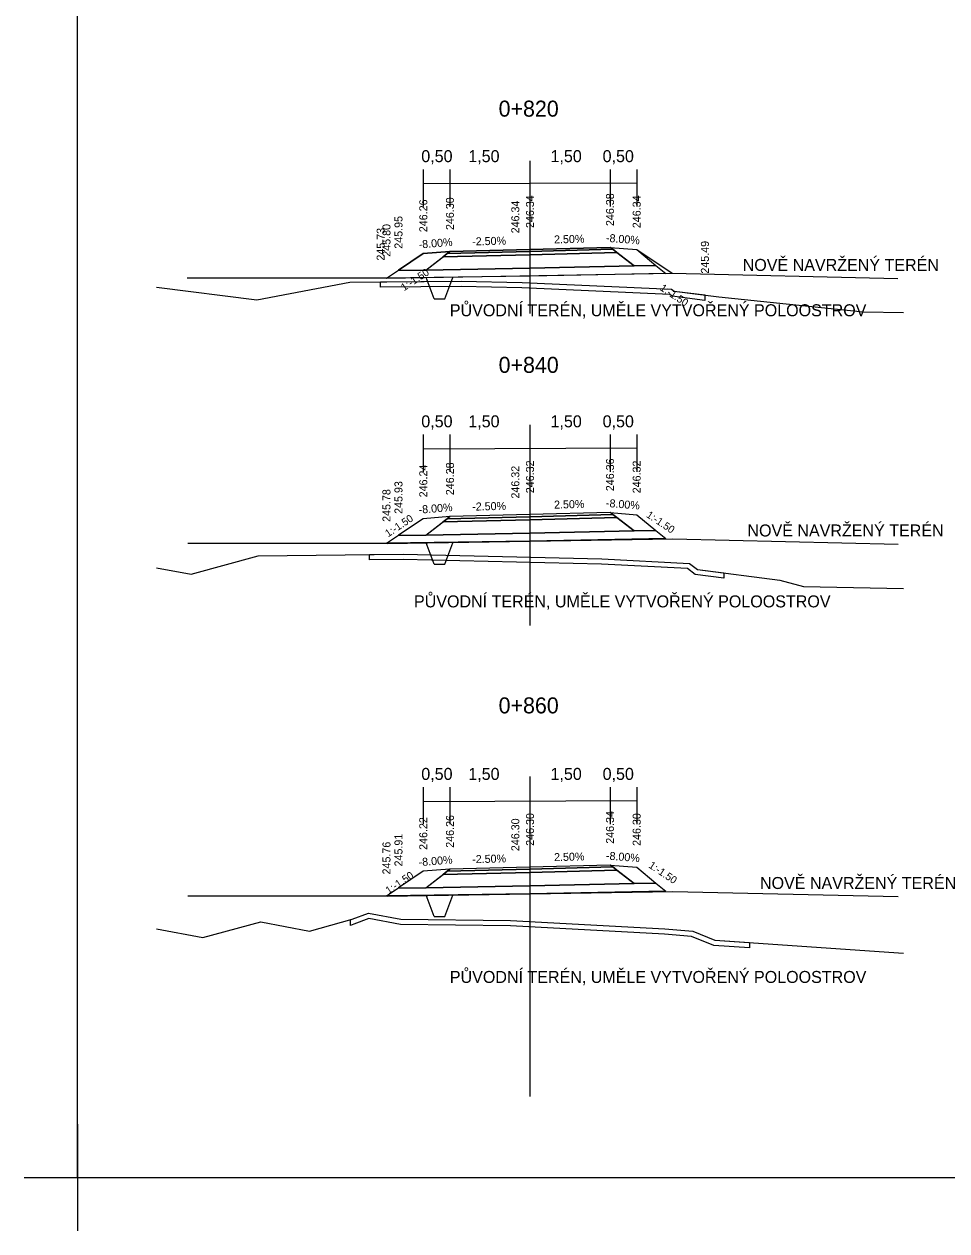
# Model space of a CAD drawing. Extents: x -552501 to -552394, y -1029983 to -1029892.
# Drawn here: x -552500.76 to -552483.46, y -1029983.45 to -1029960.83 of the extents above; entities that cross this region are included whole.
import ezdxf

# ---------------------------------------------------------------- set-up
doc = ezdxf.new("R2010")
doc.units = 0
for name, color, linetype in [('1', 7, 'Continuous'), ('16', 7, 'Continuous'), ('60', 7, 'Continuous'), ('9', 7, 'Continuous'), ('FORMATY', 7, 'Continuous'), ('Implicitní', 7, 'Continuous'), ('rámeček', 7, 'Continuous')]:
    doc.layers.add(name, color=color, linetype=linetype)

msp = doc.modelspace()

# ---------------------------------------------------------------- linework, layer by layer
for p, q in [((-552493.964, -1029965.59), (-552497.7, -1029965.59)), ((-552493.07, -1029965.98), (-552493.22, -1029965.58)), ((-552492.87, -1029965.98), (-552492.72, -1029965.58)), ((-552493.07, -1029965.98), (-552492.87, -1029965.98)), ((-552493.953, -1029970.568), (-552497.689, -1029970.568)), ((-552493.07, -1029970.95), (-552493.22, -1029970.55)), ((-552492.87, -1029970.95), (-552492.72, -1029970.55)), ((-552493.07, -1029970.95), (-552492.87, -1029970.95)), ((-552493.953, -1029977.176), (-552497.689, -1029977.176)), ((-552493.07, -1029977.559), (-552493.22, -1029977.159)), ((-552492.87, -1029977.559), (-552492.72, -1029977.159)), ((-552493.07, -1029977.559), (-552492.87, -1029977.559))]:
    msp.add_line(p, q)
for points in [[(-552493.964, -1029965.59), (-552493.739, -1029965.44), (-552493.274, -1029965.13), (-552492.774, -1029965.09), (-552491.274, -1029965.052), (-552489.774, -1029965.015), (-552489.274, -1029965.055), (-552488.606, -1029965.5)], [(-552493.964, -1029965.59), (-552488.606, -1029965.5), (-552484.38, -1029965.597)], [(-552498.274, -1029965.759), (-552496.392, -1029966), (-552494.648, -1029965.669), (-552492.561, -1029965.645), (-552491.42, -1029965.671), (-552488.619, -1029965.797), (-552488.57, -1029965.834), (-552487.737, -1029965.94), (-552485.026, -1029966.224), (-552484.274, -1029966.237)], [(-552493.953, -1029970.568), (-552488.596, -1029970.478), (-552484.37, -1029970.575)], [(-552498.274, -1029971.02), (-552497.623, -1029971.142), (-552496.369, -1029970.798), (-552493.653, -1029970.766), (-552489.927, -1029970.85), (-552488.286, -1029970.938), (-552488.137, -1029971.053), (-552486.59, -1029971.25), (-552486.147, -1029971.371), (-552484.274, -1029971.407)], [(-552493.953, -1029977.176), (-552488.596, -1029977.087), (-552484.37, -1029977.183)], [(-552498.274, -1029977.787), (-552497.407, -1029977.95), (-552496.321, -1029977.656), (-552495.405, -1029977.831), (-552494.604, -1029977.609), (-552494.301, -1029977.493), (-552493.693, -1029977.605), (-552491.638, -1029977.633), (-552488.747, -1029977.787), (-552488.22, -1029977.833), (-552487.809, -1029977.999), (-552484.274, -1029978.247)]]:
    msp.add_lwpolyline(points)
for points in [[(-552492.774, -1029965.09), (-552493.274, -1029965.13), (-552493.739, -1029965.44), (-552493.225, -1029965.44)], [(-552491.275, -1029965.092), (-552492.825, -1029965.13), (-552492.903, -1029965.19), (-552491.275, -1029965.152), (-552489.646, -1029965.109), (-552489.723, -1029965.049), (-552491.275, -1029965.092), (-552489.723, -1029965.049), (-552489.774, -1029965.015), (-552491.274, -1029965.052), (-552492.774, -1029965.09), (-552492.825, -1029965.13)], [(-552492.903, -1029965.19), (-552492.825, -1029965.13), (-552491.275, -1029965.092), (-552489.723, -1029965.049), (-552489.646, -1029965.109), (-552491.275, -1029965.152)], [(-552489.774, -1029965.015), (-552489.274, -1029965.055), (-552488.913, -1029965.353), (-552489.324, -1029965.359), (-552489.646, -1029965.109), (-552489.723, -1029965.049)], [(-552493.225, -1029965.44), (-552492.903, -1029965.19), (-552491.275, -1029965.152), (-552489.646, -1029965.109), (-552489.324, -1029965.359), (-552491.275, -1029965.402)], [(-552493.964, -1029965.59), (-552493.739, -1029965.44), (-552493.225, -1029965.44), (-552491.275, -1029965.402), (-552489.324, -1029965.359), (-552488.913, -1029965.353), (-552488.728, -1029965.503), (-552491.275, -1029965.552)], [(-552494.073, -1029965.663), (-552492.561, -1029965.645), (-552491.42, -1029965.671), (-552488.619, -1029965.797), (-552488.57, -1029965.834), (-552487.995, -1029965.907), (-552487.995, -1029966.008), (-552488.609, -1029965.93), (-552488.654, -1029965.895), (-552491.424, -1029965.771), (-552492.562, -1029965.745), (-552494.073, -1029965.763)], [(-552492.774, -1029970.06), (-552493.274, -1029970.1), (-552493.739, -1029970.41), (-552493.225, -1029970.41)], [(-552491.275, -1029970.063), (-552492.825, -1029970.1), (-552492.903, -1029970.16), (-552491.275, -1029970.123), (-552489.646, -1029970.079), (-552489.723, -1029970.019), (-552491.275, -1029970.063), (-552489.723, -1029970.019), (-552489.774, -1029969.985), (-552491.274, -1029970.023), (-552492.774, -1029970.06), (-552492.825, -1029970.1)], [(-552492.903, -1029970.16), (-552492.825, -1029970.1), (-552491.275, -1029970.063), (-552489.723, -1029970.019), (-552489.646, -1029970.079), (-552491.275, -1029970.123)], [(-552489.774, -1029969.985), (-552489.274, -1029970.025), (-552488.913, -1029970.323), (-552489.324, -1029970.329), (-552489.646, -1029970.079), (-552489.723, -1029970.019)], [(-552493.225, -1029970.41), (-552492.903, -1029970.16), (-552491.275, -1029970.123), (-552489.646, -1029970.079), (-552489.324, -1029970.329), (-552491.275, -1029970.373)], [(-552493.964, -1029970.56), (-552493.739, -1029970.41), (-552493.225, -1029970.41), (-552491.275, -1029970.373), (-552489.324, -1029970.329), (-552488.913, -1029970.323), (-552488.728, -1029970.473), (-552491.275, -1029970.523)], [(-552494.283, -1029970.773), (-552493.653, -1029970.766), (-552489.927, -1029970.85), (-552488.286, -1029970.938), (-552488.137, -1029971.053), (-552487.638, -1029971.116), (-552487.638, -1029971.217), (-552488.176, -1029971.149), (-552488.322, -1029971.037), (-552489.931, -1029970.95), (-552493.654, -1029970.866), (-552494.283, -1029970.873)], [(-552491.275, -1029976.672), (-552492.825, -1029976.709), (-552492.903, -1029976.769), (-552491.275, -1029976.732), (-552489.646, -1029976.688), (-552489.723, -1029976.628), (-552491.275, -1029976.672), (-552489.723, -1029976.628), (-552489.774, -1029976.594), (-552491.274, -1029976.632), (-552492.774, -1029976.669), (-552492.825, -1029976.709)], [(-552492.903, -1029976.769), (-552492.825, -1029976.709), (-552491.275, -1029976.672), (-552489.723, -1029976.628), (-552489.646, -1029976.688), (-552491.275, -1029976.732)], [(-552489.774, -1029976.594), (-552489.274, -1029976.634), (-552488.913, -1029976.932), (-552489.324, -1029976.938), (-552489.646, -1029976.688), (-552489.723, -1029976.628)], [(-552492.774, -1029976.669), (-552493.274, -1029976.709), (-552493.739, -1029977.019), (-552493.225, -1029977.019)], [(-552493.225, -1029977.019), (-552492.903, -1029976.769), (-552491.275, -1029976.732), (-552489.646, -1029976.688), (-552489.324, -1029976.938), (-552491.275, -1029976.982)], [(-552493.964, -1029977.169), (-552493.739, -1029977.019), (-552493.225, -1029977.019), (-552491.275, -1029976.982), (-552489.324, -1029976.938), (-552488.913, -1029976.932), (-552488.728, -1029977.082), (-552491.275, -1029977.132)], [(-552494.639, -1029977.619), (-552494.604, -1029977.609), (-552494.301, -1029977.493), (-552493.693, -1029977.605), (-552491.638, -1029977.633), (-552488.747, -1029977.787), (-552488.22, -1029977.833), (-552487.809, -1029977.999), (-552487.158, -1029978.045), (-552487.158, -1029978.145), (-552487.831, -1029978.098), (-552488.244, -1029977.931), (-552488.754, -1029977.887), (-552491.641, -1029977.733), (-552493.703, -1029977.705), (-552494.292, -1029977.597), (-552494.573, -1029977.704), (-552494.639, -1029977.723)]]:
    msp.add_lwpolyline(points, close=True)
at = {"layer": '60'}
for p, q in [((-552491.274, -1029963.394), (-552491.274, -1029966.254)), ((-552491.274, -1029968.343), (-552491.274, -1029972.102)), ((-552491.274, -1029974.93), (-552491.274, -1029980.93))]:
    msp.add_line(p, q, dxfattribs=at)
at = {"layer": '9'}
for p, q in [((-552493.274, -1029963.552), (-552493.274, -1029964.25)), ((-552492.774, -1029963.552), (-552492.774, -1029964.25)), ((-552491.274, -1029963.552), (-552491.274, -1029965.052)), ((-552489.774, -1029963.552), (-552489.774, -1029964.25)), ((-552489.274, -1029963.552), (-552489.274, -1029964.25)), ((-552493.274, -1029968.523), (-552493.274, -1029969.221)), ((-552492.774, -1029968.523), (-552492.774, -1029969.221)), ((-552491.274, -1029968.523), (-552491.274, -1029970.023)), ((-552489.774, -1029968.523), (-552489.774, -1029969.221)), ((-552489.274, -1029968.523), (-552489.274, -1029969.221)), ((-552493.274, -1029975.132), (-552493.274, -1029975.829)), ((-552492.774, -1029975.132), (-552492.774, -1029975.829)), ((-552491.274, -1029975.132), (-552491.274, -1029976.632)), ((-552489.774, -1029975.132), (-552489.774, -1029975.829)), ((-552489.274, -1029975.132), (-552489.274, -1029975.829))]:
    msp.add_line(p, q, dxfattribs=at)
at = {"layer": 'FORMATY'}
for p, q in [((-552499.755, -1029981.45), (-552499.755, -1029983.45)), ((-552500.755, -1029982.45), (-552498.755, -1029982.45))]:
    msp.add_line(p, q, dxfattribs=at)
at = {"layer": 'Implicitní'}
for p, q in [((-552493.264, -1029963.82), (-552489.274, -1029963.802)), ((-552493.264, -1029968.791), (-552489.274, -1029968.773)), ((-552493.264, -1029975.399), (-552489.274, -1029975.382))]:
    msp.add_line(p, q, dxfattribs=at)
at = {"layer": 'rámeček'}
for p, q in [((-552499.755, -1029982.45), (-552499.755, -1029952.75)), ((-552499.755, -1029981.95), (-552499.755, -1029982.45)), ((-552499.755, -1029982.45), (-552436.755, -1029982.45)), ((-552499.755, -1029982.45), (-552415.755, -1029982.45)), ((-552499.755, -1029982.45), (-552415.755, -1029982.45))]:
    msp.add_line(p, q, dxfattribs=at)

# ---------------------------------------------------------------- texts
for rotation, p in [(33.6905, (-552493.635, -1029965.839)), (326.3098, (-552488.851, -1029965.806)), (33.6901, (-552493.933, -1029970.452)), (326.3098, (-552489.106, -1029970.061)), (326.3098, (-552489.063, -1029976.631)), (33.6901, (-552493.925, -1029977.143))]:
    msp.add_text('1:-1.50', height=0.14, rotation=rotation).set_placement(p)
at = {"layer": '1'}
for s, p in [('0+820', (-552491.862, -1029962.564)), ('0+840', (-552491.862, -1029967.367)), ('0+860', (-552491.862, -1029973.75))]:
    msp.add_text(s, height=0.3, dxfattribs=at).set_placement(p)
at = {"layer": '16'}
for s, p in [('0,50', (-552493.311, -1029963.417)), ('1,50', (-552492.43, -1029963.417)), ('1,50', (-552490.889, -1029963.417)), ('0,50', (-552489.912, -1029963.417)), ('NOVĚ NAVRŽENÝ TERÉN', (-552487.287, -1029965.456)), ('PŮVODNÍ TERÉN, UMĚLE VYTVOŘENÝ POLOOSTROV', (-552492.776, -1029966.306)), ('0,50', (-552493.311, -1029968.388)), ('1,50', (-552492.43, -1029968.388)), ('1,50', (-552490.889, -1029968.388)), ('0,50', (-552489.912, -1029968.388)), ('NOVĚ NAVRŽENÝ TERÉN', (-552487.198, -1029970.434)), ('PŮVODNÍ TERÉN, UMĚLE VYTVOŘENÝ POLOOSTROV', (-552493.448, -1029971.763)), ('0,50', (-552493.311, -1029974.997)), ('1,50', (-552492.43, -1029974.997)), ('1,50', (-552490.889, -1029974.997)), ('0,50', (-552489.912, -1029974.997)), ('NOVĚ NAVRŽENÝ TERÉN', (-552486.963, -1029977.042)), ('PŮVODNÍ TERÉN, UMĚLE VYTVOŘENÝ POLOOSTROV', (-552492.776, -1029978.803))]:
    msp.add_text(s, height=0.225, dxfattribs=at).set_placement(p)
for s, rotation, p in [('246.26', 90, (-552493.199, -1029964.73)), ('246.30', 90, (-552492.699, -1029964.69)), ('246.34', 90, (-552491.474, -1029964.752)), ('246.34', 90, (-552491.199, -1029964.652)), ('246.38', 90, (-552489.699, -1029964.615)), ('246.34', 90, (-552489.199, -1029964.655)), ('245.80', 90, (-552493.889, -1029965.19)), ('245.95', 90, (-552493.664, -1029965.04)), ('245.73', 90, (-552493.998, -1029965.263)), ('-8.00%', 4.5739, (-552493.355, -1029965.036)), ('-2.50%', 1.4321, (-552492.356, -1029964.979)), ('2.50%', 1.4321, (-552490.821, -1029964.941)), ('-8.00%', 355.4261, (-552489.855, -1029964.908)), ('245.49', 90, (-552487.92, -1029965.507)), ('246.24', 90, (-552493.199, -1029969.7)), ('246.28', 90, (-552492.699, -1029969.66)), ('246.32', 90, (-552491.474, -1029969.723)), ('246.32', 90, (-552491.199, -1029969.623)), ('246.36', 90, (-552489.699, -1029969.585)), ('246.32', 90, (-552489.199, -1029969.625)), ('245.78', 90, (-552493.889, -1029970.16)), ('245.93', 90, (-552493.664, -1029970.01)), ('-8.00%', 4.5739, (-552493.355, -1029970.007)), ('-2.50%', 1.4321, (-552492.356, -1029969.95)), ('2.50%', 1.4321, (-552490.821, -1029969.912)), ('-8.00%', 355.4261, (-552489.855, -1029969.879)), ('246.22', 90, (-552493.199, -1029976.309)), ('246.26', 90, (-552492.699, -1029976.269)), ('246.30', 90, (-552491.474, -1029976.332)), ('246.30', 90, (-552491.199, -1029976.232)), ('246.34', 90, (-552489.699, -1029976.194)), ('246.30', 90, (-552489.199, -1029976.234)), ('245.76', 90, (-552493.889, -1029976.769)), ('245.91', 90, (-552493.664, -1029976.619)), ('-2.50%', 1.4321, (-552492.356, -1029976.559)), ('2.50%', 1.4321, (-552490.821, -1029976.52)), ('-8.00%', 355.4261, (-552489.855, -1029976.488)), ('-8.00%', 4.5739, (-552493.355, -1029976.615))]:
    msp.add_text(s, height=0.15, rotation=rotation, dxfattribs=at).set_placement(p)

doc.saveas('drawing.dxf')
